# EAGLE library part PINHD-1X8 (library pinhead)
PIN HEADER
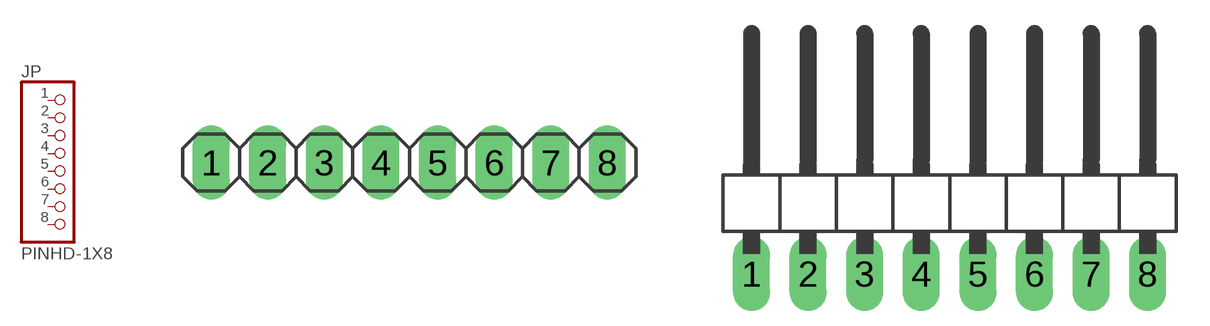
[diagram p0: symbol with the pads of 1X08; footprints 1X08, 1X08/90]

Designator prefix JP

## PINHD-1X8  [1X08]
1  1  pas
2  2  pas
3  3  pas
4  4  pas
5  5  pas
6  6  pas
7  7  pas
8  8  pas

## PINHD-1X8/90  [1X08/90]
Pads as for 1X08

## Footprint 1X08 (pad centres in mm)
PIN HEADER
drill 1.016 pad 1.67 long: 1 -8.89,0; 2 -6.35,0; 3 -3.81,0; 4 -1.27,0; 5 1.27,0; 6 3.81,0; 7 6.35,0; 8 8.89,0

## Footprint 1X08/90 (pad centres in mm)
PIN HEADER
drill 1.016 pad 1.67 long: 1 -8.89,-3.81; 2 -6.35,-3.81; 3 -3.81,-3.81; 4 -1.27,-3.81; 5 1.27,-3.81; 6 3.81,-3.81; 7 6.35,-3.81; 8 8.89,-3.81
